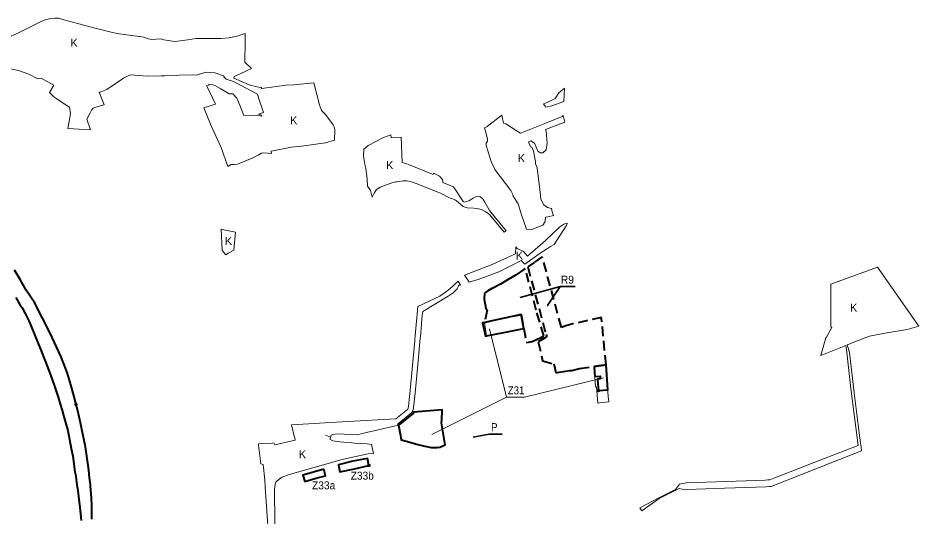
# Model space of a CAD drawing. Extents: x -650276 to -642489, y -1074311 to -1066658.
# Drawn here: x -645192 to -642489, y -1070308 to -1068813 of the extents above; entities that cross this region are included whole.
import ezdxf

# ---------------------------------------------------------------- set-up
doc = ezdxf.new("R2010")
doc.units = 0
doc.header["$LTSCALE"] = 9.6
doc.header["$PDMODE"] = 32
doc.header["$PDSIZE"] = 4.8
doc.linetypes.add('MEDIUM_DASHED', pattern=[4.5, 3, -1.5])
for name, color, linetype, lineweight in [('44', 7, 'Continuous', 40), ('45', 7, 'Continuous', 40), ('46', 7, 'Continuous', 13), ('47', 7, 'Continuous', 13), ('48', 7, 'Continuous', 13), ('60', 7, 'Continuous', 35), ('61', 7, 'MEDIUM_DASHED', 40), ('62', 7, 'Continuous', 35), ('63', 7, 'Continuous', 13)]:
    doc.layers.add(name, color=color, linetype=linetype, lineweight=lineweight)

msp = doc.modelspace()

# ---------------------------------------------------------------- linework, layer by layer
at = {"layer": '44'}
for points in [[(-645017.46, -1069970.61), (-645018.28, -1069967.49), (-645024.45, -1069944.43), (-645032.85, -1069912.07), (-645043.5, -1069878.37), (-645051.78, -1069854.2), (-645063.26, -1069825.99), (-645095.1, -1069757.62), (-645118.98, -1069710.08), (-645143.56, -1069664.05), (-645148.8, -1069656.1), (-645150.3, -1069653.84), (-645153.33, -1069649.24), (-645166.67, -1069629), (-645184.88, -1069596.58), (-645202.56, -1069568.23)], [(-645198.41, -1069650.49), (-645185.17, -1069673.38), (-645179.12, -1069681.3), (-645170.3, -1069698.91), (-645158.43, -1069722.61), (-645153.44, -1069734.71), (-645140.27, -1069766.68), (-645123.84, -1069805.38), (-645108.74, -1069843.58), (-645094.42, -1069882.65), (-645083.31, -1069913.37), (-645071.53, -1069948.89), (-645063.96, -1069973.73), (-645063.23, -1069976.2), (-645062.57, -1069978.46), (-645061.76, -1069981.21), (-645060.612, -1069985.022), (-645054.73, -1070004.56), (-645047.28, -1070031.83), (-645042.27, -1070049.23), (-645032.21, -1070102.73), (-645027.49, -1070126.56), (-645021.14, -1070173.07), (-645018.56, -1070184.92), (-645016.92, -1070196.32), (-645013.77, -1070220.04), (-645013.51, -1070222.04), (-645005.98, -1070280.14), (-645002.308, -1070319.268)], [(-645010.54, -1069999.3), (-645015.548, -1069978.177), (-645016.01, -1069976.23), (-645016.89, -1069972.82), (-645017.46, -1069970.61)], [(-644970.524, -1070315.358), (-644970.36, -1070275.49), (-644971.47, -1070250.14), (-644974, -1070216.2), (-644974.29, -1070213.17), (-644974.49, -1070210.98), (-644976.94, -1070191.41), (-644978.49, -1070180.05), (-644979.57, -1070167.9), (-644984.21, -1070132.81), (-644989.62, -1070097.79), (-644996.88, -1070059.73), (-645004.02, -1070026.44), (-645010.54, -1069999.3)]]:
    msp.add_lwpolyline(points, dxfattribs=at)
msp.add_point((-645017.46, -1069970.61), dxfattribs=at)
at = {"layer": '45'}
for p, q in [((-644138.78, -1070154.07), (-644143.31, -1070132.95)), ((-644182.31, -1070163.66), (-644138.78, -1070154.07))]:
    msp.add_line(p, q, dxfattribs=at)
for points in [[(-643791.88, -1069725.25), (-643797.75, -1069726.51), (-643789.3, -1069766.05), (-643786.35, -1069765.46), (-643764.94, -1069761.27), (-643729.34, -1069754.3), (-643674.3, -1069743.53), (-643682.61, -1069701.16)], [(-643791.88, -1069725.25), (-643797.75, -1069726.51), (-643789.3, -1069766.05), (-643786.35, -1069765.46), (-643764.94, -1069761.27), (-643729.34, -1069754.3), (-643674.3, -1069743.53), (-643682.61, -1069701.16)], [(-643920.84, -1070026.46), (-643920.29, -1070017.73), (-643920.16, -1070015.69), (-643918.69, -1069992.23), (-643918.88, -1069986.82), (-644004.06, -1069994.59), (-644005.92, -1069998.62), (-644044.7, -1070029.04), (-644050.12, -1070033.64), (-644044.18, -1070064.43), (-644041.71, -1070077.29), (-644022.77, -1070082.66), (-643991.99, -1070091.37), (-643971.03, -1070095.79), (-643951.99, -1070100.35), (-643933.96, -1070100.18), (-643926.33, -1070099.5), (-643909.87, -1070091.95)], [(-643920.84, -1070026.46), (-643920.29, -1070017.73), (-643920.16, -1070015.69), (-643918.69, -1069992.23), (-643918.88, -1069986.82), (-644004.06, -1069994.59), (-644005.92, -1069998.62), (-644044.7, -1070029.04), (-644050.12, -1070033.64), (-644044.18, -1070064.43), (-644041.71, -1070077.29), (-644022.77, -1070082.66), (-643991.99, -1070091.37), (-643971.03, -1070095.79), (-643951.99, -1070100.35), (-643933.96, -1070100.18), (-643926.33, -1070099.5), (-643909.87, -1070091.95)], [(-644274.246, -1070164.59), (-644337.256, -1070182.64), (-644331.096, -1070202.4), (-644294.206, -1070190.9), (-644269.036, -1070184.57)], [(-644274.246, -1070164.59), (-644337.256, -1070182.64), (-644331.096, -1070202.4), (-644294.206, -1070190.9), (-644269.036, -1070184.57)]]:
    msp.add_lwpolyline(points, close=True, dxfattribs=at)
for points in [[(-643450.3, -1069929.7), (-643422.204, -1069927.68), (-643427.6, -1069852.59), (-643463.51, -1069857.44)], [(-643463.51, -1069857.44), (-643463.31, -1069860.18), (-643461.327, -1069887.84)], [(-643461.327, -1069887.84), (-643445.37, -1069886.7), (-643444.79, -1069894.68), (-643452.77, -1069895.25), (-643451.74, -1069909.63), (-643450.3, -1069929.7)], [(-644143.31, -1070132.95), (-644143.31, -1070132.95), (-644143.31, -1070132.95), (-644187.11, -1070141.58), (-644230.4, -1070152.08), (-644226.23, -1070173.28), (-644182.31, -1070163.66)], [(-644143.31, -1070132.95), (-644143.31, -1070132.95), (-644143.31, -1070132.95), (-644187.11, -1070141.58), (-644230.4, -1070152.08), (-644226.23, -1070173.28), (-644182.31, -1070163.66)], [(-644182.31, -1070163.66), (-644138.78, -1070154.07), (-644143.31, -1070132.95)]]:
    msp.add_lwpolyline(points, dxfattribs=at)
for p in [(-643450.3, -1069929.7), (-644138.78, -1070154.07)]:
    msp.add_point(p, dxfattribs=at)
at = {"layer": '46'}
for points in [[(-643672.005, -1069949.473), (-643725.65, -1069949.473), (-643725.65, -1069949.473), (-643777.096, -1069744.435), (-643725.65, -1069949.473), (-643950.635, -1070061)], [(-643434.663, -1069891.167), (-643672.005, -1069949.473), (-643725.65, -1069949.473)]]:
    msp.add_lwpolyline(points, dxfattribs=at)
at = {"layer": '47'}
msp.add_line((-643785.6, -1069166.98), (-643782.92, -1069176.24), dxfattribs=at)
for points in [[(-645239.85, -1068880.94), (-645190.22, -1068857.23), (-645124.36, -1068824.11), (-645112.77, -1068819.13), (-645093.56, -1068814.27), (-645081.12, -1068813.15), (-645070.05, -1068814), (-645053.97, -1068818.31), (-644964.45, -1068842.38), (-644908.26, -1068856.91), (-644887.91, -1068860.82), (-644834.84, -1068867.4), (-644814.47, -1068870.12), (-644800.87, -1068874.97), (-644790.41, -1068877.73), (-644763.04, -1068875.63), (-644753.71, -1068878.41), (-644721.29, -1068883.2), (-644681.99, -1068878.15), (-644658.39, -1068874.59), (-644636.55, -1068874.02), (-644608.71, -1068874.78), (-644583.26, -1068874.26), (-644557.75, -1068872.33), (-644533.84, -1068867.2), (-644510.62, -1068859.35), (-644510.567, -1068897.909), (-644510.75, -1068931.16), (-644511.47, -1068945.37), (-644491.31, -1068964.35), (-644523.4, -1068978.98), (-644543.05, -1068988.64), (-644544.02, -1068993.75), (-644498.28, -1069013.19), (-644475.09, -1069018.99), (-644461.74, -1069020.83), (-644459.67, -1069024.41), (-644387.91, -1069014.64), (-644364.53, -1069012.83), (-644304.6, -1069007.55), (-644286.94, -1069073.19)], [(-645131.73, -1068995.69), (-645159.37, -1068981.11), (-645189.84, -1068969.91), (-645229.27, -1068962.28), (-645232.4, -1068961.67), (-645255.21, -1068962.49), (-645275.45, -1068964.38), (-645292.77, -1068966.91), (-645311.99, -1068972.74), (-645328.55, -1068980.37), (-645350.17, -1068993.33), (-645371.35, -1069010.64), (-645396.53, -1069030.88)], [(-644473.222, -1069040.994), (-644545.54, -1069003.12), (-644567.09, -1068996.26), (-644572.05, -1068991.08), (-644575.29, -1068986.48), (-644600.67, -1068977.77), (-644627.41, -1068975.6), (-644657.61, -1068983.91), (-644667.57, -1068983.47), (-644708.6, -1068984.54), (-644750.67, -1068986.34), (-644761.88, -1068986.27), (-644803.31, -1068986.97), (-644855.56, -1068983.38), (-644875.57, -1068993.47), (-644925.35, -1069027.75), (-644944.9, -1069035.04), (-644948.575, -1069035.675)], [(-644948.575, -1069035.675), (-644941.27, -1069052.9), (-644932.95, -1069073.65), (-644958.25, -1069079.99), (-644965.95, -1069083.67), (-644970.84, -1069088.8), (-644975.56, -1069097.564), (-644985.15, -1069116.67), (-644974.34, -1069147.85), (-645041.751, -1069143.816), (-645034.13, -1069099.79), (-645036.87, -1069079.78), (-645052.83, -1069070.4), (-645075.206, -1069055.523), (-645084.19, -1069049.55), (-645096.97, -1069036.63), (-645084.17, -1069013.922), (-645122.25, -1068993.21), (-645131.73, -1068995.69)], [(-644286.94, -1069073.19), (-644281.26, -1069090.19), (-644269.11, -1069102.31), (-644245.65, -1069133.66), (-644243.14, -1069139.47), (-644240.67, -1069148.58), (-644242.48, -1069179.49), (-644268.7, -1069187.42), (-644340.83, -1069197.13), (-644371.08, -1069199.84), (-644432.53, -1069212.02), (-644430.91, -1069218.82), (-644454.87, -1069217.05), (-644460.97, -1069217.61), (-644470.64, -1069224), (-644489.27, -1069233.04), (-644532.71, -1069251.12), (-644541.83, -1069251.66), (-644552.01, -1069252.24), (-644562.47, -1069257.56), (-644582.29, -1069201.27), (-644612.3, -1069136.45), (-644614.41, -1069131.08), (-644633.66, -1069082), (-644598.81, -1069071.02), (-644619.54, -1069029.55), (-644625.69, -1069015.84), (-644618.8, -1069014.7), (-644619.1, -1069011.81), (-644607.16, -1069013.56), (-644601.43, -1069015.74), (-644583.05, -1069025.29), (-644563.19, -1069037.21), (-644558.56, -1069039.86), (-644553.62, -1069040.53), (-644547.31, -1069040.11), (-644535.13, -1069053.18), (-644525.83, -1069073.84), (-644514.47, -1069105.62), (-644474.33, -1069104.22), (-644459.82, -1069106.73), (-644461.01, -1069104.36), (-644470.37, -1069101.55), (-644454.75, -1069096.51), (-644469.28, -1069054.8), (-644473.222, -1069040.994)], [(-643697.29, -1069149.7), (-643728.49, -1069129.95), (-643734.75, -1069128.3), (-643739.66, -1069104.58), (-643747.75, -1069110.71), (-643779.31, -1069134.63), (-643784.55, -1069137.77), (-643792.04, -1069142.27), (-643785.6, -1069166.98)], [(-643555.98, -1069105.57), (-643559.5, -1069107.98), (-643610.81, -1069129.04), (-643681.63, -1069157.04), (-643683.68, -1069157.86), (-643697.29, -1069149.7)], [(-643607.02, -1069152.34), (-643609.08, -1069147.64), (-643550.79, -1069125.24), (-643555.98, -1069105.57)], [(-644094.79, -1069171.27), (-644141.24, -1069195.17), (-644154.36, -1069206.06), (-644155.37, -1069226.72), (-644151.11, -1069250.7), (-644148.22, -1069263.22), (-644144.05, -1069295.67)], [(-644024.93, -1069250.23), (-644038.83, -1069245.65), (-644042.37, -1069169.77), (-644071.97, -1069171.72), (-644073.35, -1069162.84), (-644094.79, -1069171.27)], [(-643707.23, -1069344.52), (-643691.6, -1069370.3), (-643681.09, -1069403.24), (-643665.87, -1069446.1), (-643650.28, -1069446.91), (-643616.78, -1069433.81), (-643610.18, -1069422.91), (-643609.6, -1069409.99), (-643601.9, -1069408.43), (-643585.19, -1069404.76), (-643589.52, -1069393.88), (-643590.89, -1069383.9), (-643602.92, -1069380.53), (-643614.35, -1069373.28), (-643623.28, -1069355.47), (-643625.9, -1069326.77), (-643634.56, -1069262.02), (-643639.23, -1069250.38), (-643638.72, -1069242.94), (-643645.61, -1069212.25), (-643649.84, -1069200.4), (-643654.57, -1069198.77), (-643660.22, -1069184.11), (-643653.05, -1069180.98), (-643641.84, -1069187.68), (-643631.66, -1069211.67), (-643624.38, -1069217.27), (-643617.64, -1069217), (-643607.37, -1069208.43), (-643604.38, -1069188.48), (-643607.02, -1069152.34)], [(-643782.92, -1069176.24), (-643783.2, -1069181.85), (-643786.97, -1069188.11), (-643786.89, -1069195.02), (-643771.86, -1069242.77), (-643761.21, -1069267.12), (-643712.78, -1069330.24)], [(-643732.705, -1069454.79), (-643726.74, -1069450.72), (-643777.27, -1069389.71), (-643791.02, -1069364.54), (-643798.1, -1069353.51), (-643804.83, -1069348.99), (-643817.06, -1069348.14), (-643826.21, -1069352.92), (-643838.69, -1069360.79), (-643853.56, -1069364.44), (-643856.43, -1069362.68), (-643885.63, -1069318.72), (-643916.78, -1069305.89), (-643917.36, -1069302.04), (-643918.08, -1069297.33), (-643926.74, -1069287.37), (-643944.89, -1069278.32), (-643946.16, -1069281.84), (-644015.12, -1069254.24), (-644024.93, -1069250.23)], [(-644144.05, -1069295.67), (-644143.54, -1069317.05), (-644138.55, -1069324.23), (-644134.15, -1069330.45), (-644132.52, -1069338.02), (-644129.09, -1069349.83), (-644123.21, -1069338.41), (-644116.33, -1069327.36), (-644105.5, -1069320.03), (-644067.08, -1069306.15)], [(-644067.08, -1069306.15), (-644058.05, -1069304.02), (-644054.35, -1069303.55)], [(-644054.35, -1069303.55), (-644035.89, -1069301.02), (-644025.24, -1069301.38), (-644014.19, -1069303.36), (-643993.91, -1069309.57), (-643936.87, -1069332.93), (-643924.42, -1069338.29), (-643894.84, -1069352.76), (-643885.22, -1069355.58), (-643879.48, -1069359.13), (-643876.34, -1069360.61), (-643856.58, -1069377.59), (-643844.28, -1069382.26), (-643823.72, -1069382.61), (-643815.93, -1069384.23), (-643801.36, -1069387.23), (-643788.63, -1069393.7), (-643776.78, -1069401.87), (-643732.705, -1069454.79)], [(-643712.78, -1069330.24), (-643705.74, -1069343.54), (-643707.23, -1069344.52)], [(-643671.53, -1069551.1), (-643649.94, -1069535.93), (-643624.65, -1069517.85), (-643605.97, -1069505.47), (-643594.49, -1069498.17), (-643582.77, -1069491.76), (-643545.07, -1069432.89), (-643544.06, -1069427.6), (-643553.7, -1069430.44), (-643565.92, -1069438.4), (-643608.89, -1069479.72), (-643663.46, -1069526.87), (-643675.32, -1069512.62), (-643693.95, -1069503.38)], [(-643693.95, -1069503.38), (-643697.85, -1069499.21), (-643699.23, -1069519.48), (-643769.08, -1069551.96), (-643852.51, -1069584.08), (-643845.304, -1069594.087)], [(-643845.304, -1069594.087), (-643837.72, -1069604.62), (-643822.06, -1069600.07), (-643811.16, -1069596.45), (-643749.64, -1069573.35), (-643709.33, -1069554.14), (-643682.27, -1069539.41), (-643671.53, -1069551.1)], [(-642704.1, -1069793.095), (-642703.57, -1069792.88), (-642693.99, -1069788.85), (-642637.44, -1069766.81), (-642589.86, -1069757.1), (-642524.14, -1069746.8), (-642488.71, -1069736.85), (-642613.34, -1069559.68), (-642753.18, -1069610.65), (-642753.25, -1069738.59), (-642750.08, -1069740.57), (-642766.27, -1069769), (-642767.89, -1069771.42), (-642782.69, -1069824.93)], [(-644399.15, -1070188.55), (-644381.21, -1070181.71), (-644218.65, -1070135.75), (-644188.44, -1070129.43), (-644140.72, -1070119.57), (-644125, -1070117.83), (-644130.91, -1070091.1), (-644144.13, -1070089.47), (-644181.81, -1070087.51), (-644191.26, -1070086.47), (-644225.13, -1070082.95), (-644247.3, -1070079.69), (-644256.54, -1070075.02), (-644255.52, -1070072.5), (-644254.136, -1070069.079), (-644254.13, -1070069.08), (-644254.25, -1070069.37), (-644269.156, -1070063.55), (-644254.25, -1070069.37), (-644251.9, -1070063.55), (-644248.05, -1070061.33), (-644233.51, -1070059.54), (-644174.12, -1070062.16), (-644159.02, -1070057.84), (-644050.12, -1070033.64), (-644053.18, -1070030.57), (-644051.913, -1070029.549), (-644049.311, -1070027.453), (-644009.95, -1069995.74), (-644006.96, -1069990.34), (-644005.06, -1069981.28), (-644003.06, -1069964.06), (-644000.52, -1069937.19), (-643992.27, -1069851.31), (-643984.845, -1069772.863), (-643984.44, -1069768.58), (-643978.85, -1069703.4), (-643977.454, -1069692.683), (-643901.55, -1069646.92), (-643886.62, -1069636.87), (-643873.82, -1069625.05), (-643872.55, -1069620.75), (-643870.44, -1069613.56), (-643863.92, -1069613.9), (-643870.697, -1069601.241), (-643895.951, -1069625.069), (-643909.616, -1069634.267), (-643926.229, -1069646.367), (-643992.34, -1069677.76), (-643994.36, -1069701.05), (-643995.17, -1069710.42), (-643999.94, -1069765.62), (-644000.79, -1069775.42), (-644001.04, -1069778.063), (-644001.29, -1069780.7), (-644016.47, -1069938.99), (-644017.15, -1069945.93), (-644020.26, -1069978.38), (-644022.43, -1069984.87), (-644022.99, -1069986.58), (-644058.55, -1070014.4), (-644219.33, -1070023.53), (-644370.87, -1070032.13), (-644361.74, -1070070.32), (-644361.55, -1070070.345), (-644360.41, -1070077.91), (-644421.26, -1070091.99), (-644423.99, -1070086.17), (-644433.19, -1070088.37), (-644470.17, -1070089.43), (-644470.55, -1070093.61), (-644463.28, -1070149.42), (-644456.41, -1070151.18), (-644450.72, -1070196.97), (-644450.15, -1070219.06), (-644445.28, -1070290.84), (-644440.36, -1070362.62)], [(-642662.32, -1070100.64), (-642663.28, -1070092.67), (-642667.19, -1070063.71), (-642682.78, -1069935.98), (-642697.64, -1069815.14), (-642698.77, -1069809.17), (-642700.34, -1069804.12), (-642704.1, -1069793.095)], [(-642706.3, -1069806.69), (-642693.2, -1069922.89), (-642671.23, -1070094.16), (-642801.19, -1070143.75), (-642921.03, -1070191.32), (-642936.02, -1070197.23), (-642942.12, -1070197.4), (-642950.42, -1070197.58), (-643066.26, -1070201.69), (-643187.06, -1070205.98)], [(-642782.69, -1069824.93), (-642708.257, -1069794.779), (-642706.3, -1069806.69)], [(-642936.88, -1070217.27), (-642931.88, -1070217.1), (-642792.87, -1070162.36), (-642661.13, -1070110.48), (-642662.32, -1070100.64)], [(-644243.15, -1070849.89), (-644246.93, -1070850.52), (-644282.77, -1070863.19), (-644324.34, -1070877.71), (-644337.15, -1070878.64), (-644344.86, -1070875.09), (-644460.82, -1070727.21), (-644465.31, -1070713.25), (-644468.1, -1070704.23), (-644467.84, -1070682.37), (-644466.998, -1070678.065), (-644463.28, -1070659.06), (-644458.85, -1070579.04), (-644455.2, -1070554.88), (-644418.69, -1070433.36), (-644418.23, -1070415.62), (-644421.45, -1070325.29), (-644422.5, -1070226.42), (-644420.14, -1070208.56), (-644418.61, -1070204.51), (-644417.36, -1070203.24), (-644407.55, -1070194.16), (-644399.15, -1070188.55)], [(-643187.06, -1070205.98), (-643207.1, -1070209.72), (-643219.4, -1070225.8), (-643267.55, -1070249.49), (-643326.26, -1070281.43), (-643320, -1070290.2), (-643267.75, -1070252.77), (-643208.09, -1070223.14), (-643190.42, -1070226.99)], [(-643190.42, -1070226.99), (-643184.86, -1070225.91), (-643071.16, -1070221.95), (-642947.42, -1070217.64), (-642936.88, -1070217.27)]]:
    msp.add_lwpolyline(points, dxfattribs=at)
for points in [[(-643589.94, -1069076.36), (-643554.17, -1069063.59), (-643551.72, -1069023.19), (-643569.44, -1069037.24), (-643580.21, -1069053.96), (-643603.72, -1069066.5), (-643614.36, -1069070.29), (-643614.82, -1069070.45), (-643610.31, -1069077.52), (-643608.65, -1069080.11)], [(-644578.92, -1069446.8), (-644581.87, -1069446.28), (-644579.047, -1069509.608), (-644567.976, -1069522.752), (-644561.24, -1069518.27), (-644543.99, -1069508.88), (-644539, -1069454.88)]]:
    msp.add_lwpolyline(points, close=True, dxfattribs=at)
at = {"layer": '60'}
msp.add_lwpolyline([(-643738.691, -1070059.84), (-643778.124, -1070059.84), (-643826.476, -1070069.235)], dxfattribs=at)
msp.add_lwpolyline([(-643738.691, -1070059.84), (-643778.124, -1070059.84), (-643826.476, -1070069.235)], dxfattribs=at)
at = {"layer": '61'}
for points in [[(-643561.41, -1069740.406), (-643618.737, -1069528.647), (-643643.16, -1069545.42), (-643662.335, -1069558.944), (-643607.44, -1069761.72), (-643605.24, -1069768.92), (-643612.22, -1069772.9), (-643630.77, -1069783.44), (-643618, -1069840.01), (-643584.63, -1069849.66), (-643578.28, -1069874.97), (-643574.05, -1069875.85), (-643567.91, -1069874.7), (-643548.67, -1069871.08), (-643535.83, -1069869.23), (-643530.01, -1069869.17), (-643507.1, -1069863.33), (-643463.51, -1069857.44), (-643427.6, -1069852.59), (-643440.77, -1069713.85), (-643441.08, -1069710.59), (-643527.49, -1069729.78), (-643547.9, -1069735.62)], [(-643743.81, -1069610.19), (-643770.29, -1069624.14), (-643781.95, -1069630.63), (-643791.77, -1069637.88), (-643793.09, -1069656.07), (-643788.14, -1069682.71), (-643784.59, -1069688.47), (-643791.88, -1069725.25), (-643682.61, -1069701.16), (-643674.3, -1069743.53), (-643665.92, -1069785.96), (-643649.25, -1069782.43), (-643621.71, -1069770.11), (-643613.9, -1069765.6), (-643637.36, -1069688.73), (-643669.73, -1069564.16), (-643673.82, -1069567.04), (-643697, -1069582.64), (-643721.43, -1069596.72)]]:
    msp.add_lwpolyline(points, close=True, dxfattribs=at)
at = {"layer": '62'}
msp.add_lwpolyline([(-643519.721, -1069617.808), (-643564.914, -1069617.808), (-643602.876, -1069674.79), (-643564.914, -1069617.808), (-643685.127, -1069650.369)], dxfattribs=at)
at = {"layer": '62', "lineweight": 13}
msp.add_lwpolyline([(-643519.721, -1069617.808), (-643564.914, -1069617.808), (-643602.876, -1069674.79), (-643564.914, -1069617.808), (-643685.127, -1069650.369)], dxfattribs=at)
at = {"layer": '63'}
for points in [[(-643674.3, -1069743.53), (-643682.61, -1069701.16), (-643791.88, -1069725.25), (-643786.35, -1069765.46)], [(-643786.35, -1069765.46), (-643729.34, -1069754.3), (-643674.3, -1069743.53)], [(-643452.63, -1069967.09), (-643446.63, -1069966), (-643419.62, -1069963.66), (-643420.79, -1069947.35), (-643427.6, -1069852.59), (-643463.51, -1069857.44), (-643459.13, -1069918.47)], [(-643459.13, -1069918.47), (-643456.14, -1069918.26), (-643452.63, -1069967.09)], [(-643918.88, -1069986.82), (-644004.06, -1069994.59), (-644005.92, -1069998.62), (-644050.12, -1070033.64), (-644041.71, -1070077.29)], [(-644041.71, -1070077.29), (-644041.71, -1070077.29), (-644022.77, -1070082.66), (-644003.7, -1070088.06), (-643991.99, -1070091.37), (-643971.03, -1070095.79), (-643951.99, -1070100.35), (-643933.96, -1070100.18), (-643926.33, -1070099.5), (-643909.87, -1070091.95), (-643920.84, -1070026.46), (-643920.29, -1070017.73), (-643920.16, -1070015.69), (-643918.69, -1069992.23), (-643918.88, -1069986.82)], [(-644143.31, -1070132.95), (-644187.11, -1070141.58), (-644230.4, -1070152.08), (-644226.23, -1070173.28)], [(-644182.31, -1070163.66), (-644138.78, -1070154.07), (-644143.31, -1070132.95)], [(-644226.23, -1070173.28), (-644182.31, -1070163.66), (-644182.31, -1070163.66)]]:
    msp.add_lwpolyline(points, dxfattribs=at)
msp.add_lwpolyline([(-644295.01, -1070190.9), (-644269.84, -1070184.57), (-644275.05, -1070164.59), (-644338.06, -1070182.64), (-644331.9, -1070202.4)], close=True, dxfattribs=at)

# ---------------------------------------------------------------- texts
at = {"layer": '46'}
for s, width, p in [('Z31', 0.9, (-643722.294, -1069940.847)), ('Z33b', 0.95, (-644193.607, -1070196.61)), ('Z33b', 0.95, (-644193.607, -1070196.61)), ('Z33a', 0.95, (-644309.424, -1070225.565)), ('Z33a', 0.95, (-644309.424, -1070225.565))]:
    msp.add_text(s, height=24, dxfattribs=dict(at, width=width)).set_placement(p)
at = {"layer": '48'}
for p in [(-645034.002, -1068899.33), (-644374.971, -1069131.317), (-643691.928, -1069244.995), (-644086.887, -1069265.894), (-644570.824, -1069493.226), (-644570.824, -1069493.226), (-643697.851, -1069536.996), (-642695.251, -1069693.065), (-644348.839, -1070132.426)]:
    msp.add_text('K', height=24, dxfattribs=at).set_placement(p)
at = {"layer": '60', "width": 0.9}
msp.add_text('P', height=24, dxfattribs=at).set_placement((-643772.431, -1070051.2))
msp.add_text('P', height=24, dxfattribs=at).set_placement((-643772.431, -1070051.2))
at = {"layer": '62', "width": 0.95}
msp.add_text('R9', height=24, dxfattribs=at).set_placement((-643562.88, -1069609.148))
msp.add_text('R9', height=24, dxfattribs=at).set_placement((-643562.88, -1069609.148))

doc.saveas('drawing.dxf')
